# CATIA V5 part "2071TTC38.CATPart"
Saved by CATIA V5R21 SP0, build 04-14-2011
Part number: 2071TTC38
Bounding box of the stored display mesh (mm): x -10 to 10, y 0 to 1000, z -14.5 to 12.5
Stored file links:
  C:\Users\ALI OZGUN\Desktop\alhan\PROFILLER\2071TTC38.CATPart
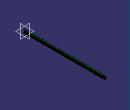
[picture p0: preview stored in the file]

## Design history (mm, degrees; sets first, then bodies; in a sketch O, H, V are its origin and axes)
Body1 (main body)
  Sketch1 on zx-plane, origin (0, 0, 0), H (-1, 0, 0), V (0, 0, 1)
    line L1 (10, 11) -> (10, -12.5)
    line L2 (10, -12.5) -> (-10, -12.5)
    line L3 (-10, -12.5) -> (-10, -0.7)
    line L4 (-10, 12.5) -> (-4.6, 12.5)
    point P4 (-10, 2.6)
    line L5 (-4.6, -0.7) -> (-10, -0.7)
    line L6 (-10, 5.9) -> (-4.6, 5.9)
    point P5 (-9.0936, 12.527)
    point P6 (-2.35, 2.6)
    line L7 (-0.1, 7.35) -> (-0.1, -2.15)
    line L8 (-0.1, -2.15) -> (-4.6, -2.15)
    line L9 (-4.6, -2.15) -> (-4.6, -0.7)
    line L10 (-4.6, 7.35) -> (-0.1, 7.35)
    line L11 (10, 11) -> (-4.6, 11)
    line L12 (-4.6, 11) -> (-4.6, 12.5)
    axis line L13 (-44.5224, 2.6) -> (23.1973, 2.6)
    line L14 (-10, 5.9) -> (-10, 12.5)
    point P18 (-4.6, 5.9)
    line L15 (-4.6, 5.9) -> (-4.6, 7.35)
    distance L6 L5 = 6.6
    distance L10 L8 = 9.5
    distance L7 L9 = 4.5
    distance L12 L3 = 5.4
    distance L1 L3 = 20
    distance L4 L2 = 25
    distance L11 L4 = 1.5
    distance L13 L4 = 9.9
    vertical: L1 V, L3 V, L7 V, L9 V, L12 V, L14 V, L15 V
    horizontal: L2 H, L4 H, L5 H, L6 H, L8 H, L10 H, L11 H, L13 H
    equidistance: L1 L3 O, L2 L4 O, L5 L6 P4, L7 L9 P6, L8 L10 P6
    coincidence: P4 L3, L9 L12, L3 L14, L9 P18, L9 L15
    symmetry: L6 L5 L13, L8 L10 L13
  Pad1: profile Sketch1, direction (0, 1, 0), length 1000
  Body2
    Solid1: linked copy from another document
  Remove1: tool Body2
  RemoveFace1: RemoveFaces (face of Solid1; face of Solid1)
Body3
  Sketch2 on start face of Pad1, origin (0, 0, 0), H (1, 0, 0), V (0, 0, 1)
    point P1 (-5, -4.5)
    line L1 (-5, -4.5) -> (-9, -4.5)
    line L2 (-10, -5.5) -> (-10, -13.5)
    line L3 (-9, -14.5) -> (9, -14.5)
    line L4 (10, -13.5) -> (10, -5.5)
    point P2 (10, -4.5)
    line L5 (9, -4.5) -> (5, -4.5)
    point P3 (5, -4.5)
    reference projected line E1 (4.6, 12.5) -> (10, 12.5) from edge [start face of Pad1 | face of Pad1 from Sketch1.L4]
    arc A1 centre (-9, -5.5) radius 1 from (-9, -4.5) to (-10, -5.5) ccw
    arc A2 centre (-9, -13.5) radius 1 from (-10, -13.5) to (-9, -14.5) ccw
    arc A3 centre (9, -13.5) radius 1 from (9, -14.5) to (10, -13.5) ccw
    arc A4 centre (9, -5.5) radius 1 from (10, -5.5) to (9, -4.5) ccw
    distance L4 L2 = 20
    distance L3 L5 = 10
    distance L3 E1 = 27
    radius A1 = 1
    radius A2 = 1 {= Sketch2.radius(A1)}
    radius A3 = 1 {= Sketch2.radius(A1)}
    radius A4 = 1 {= Sketch2.radius(A1)}
    distance P3 P1 = 10
    horizontal: L1 H, L3 H, L5 H
    vertical: L2 V, L4 V
    coincidence: P2 L1, L4 P2, L5 P2
    symmetry: L5 L1 V, L4 L2 V, P3 P1 V
    tangency: A1 L1, A1 L2, A2 L2, A2 L3, A3 L3, A3 L4, A4 L4, A4 L5
  Pad2: profile Sketch2, direction (0, 1, 0), length 1000, thin wall 1.5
